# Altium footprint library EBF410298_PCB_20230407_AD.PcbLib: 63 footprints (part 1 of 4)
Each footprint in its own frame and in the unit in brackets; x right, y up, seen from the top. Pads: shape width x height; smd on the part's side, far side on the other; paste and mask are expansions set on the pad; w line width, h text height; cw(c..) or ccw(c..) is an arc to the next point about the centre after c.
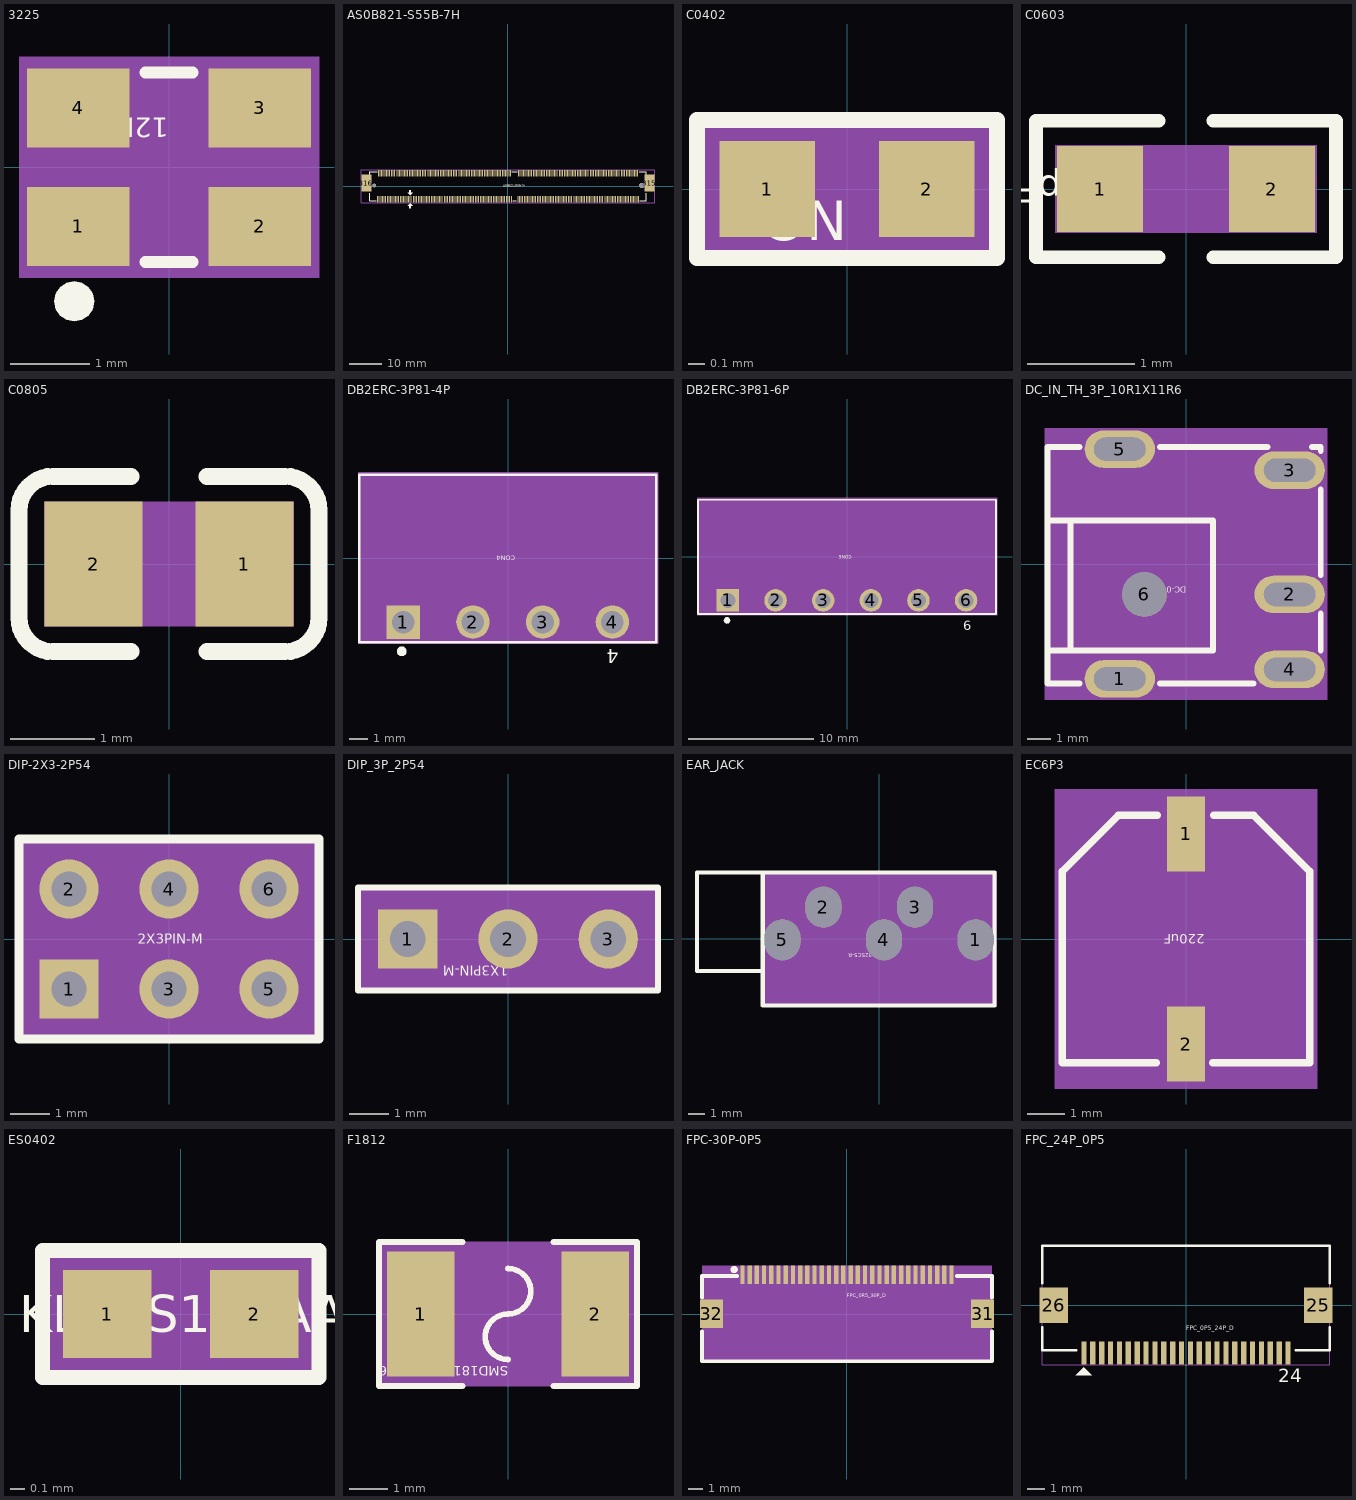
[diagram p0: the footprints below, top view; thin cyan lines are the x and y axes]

## 3225 [mm] "3225"
pads (4):
  rect 1.3x1 smd: 1(-1.15,-0.75) 2(1.15,-0.75) 3(1.15,0.75) 4(-1.15,0.75)
Top Overlay:
  dashed: -1.2,-1.955 -1.298,-1.935 -1.38,-1.88 -1.435,-1.798 -1.455,-1.7 -1.435,-1.602 -1.417,-1.575 -1.38,-1.52 -1.298,-1.465 -1.2,-1.445 -1.102,-1.465 -1.02,-1.52 -0.983,-1.575 -0.965,-1.602 -0.945,-1.7 -0.965,-1.798 -1.02,-1.88 -1.102,-1.935
  lines w0.15: -0.3,-1.2 0.3,-1.2 ; -0.3,1.2 0.3,1.2
  text "12MHz" at 0,0.625 h0.25
Top 3D Body:
  region: -1.9,1.4 -1.9,-1.4 1.9,-1.4 1.9,1.4
Mechanical 17:
  text "1" at -1.15,-0.394 h0.89
  text "3" at 1.15,1.106 h0.89
  text "2" at 1.15,-0.394 h0.89
  text "4" at -1.15,1.106 h0.89
Top Assembly:
  lines w0.15: -1.6,-1.25 -1.6,1.25 1.6,1.25 1.6,-1.25 -1.6,-1.25
3D body: height 3.81, standoff 0, extent -1.9,-1.4 1.9,1.4

## AS0B821-S55B-7H [mm] "AS0B821-S55B-7H"
pads (318):
  rect 0.3x2 smd: 1(-40,-3.95) 2(-39.75,3.95) 3(-39.5,-3.95) 4(-39.25,3.95) 5(-39,-3.95) 6(-38.75,3.95) 7(-38.5,-3.95) 8(-38.25,3.95) 9(-38,-3.95) 10(-37.75,3.95) 11(-37.5,-3.95) 12(-37.25,3.95) 13(-37,-3.95) 14(-36.75,3.95) 15(-36.5,-3.95) 16(-36.25,3.95) 17(-36,-3.95) 18(-35.75,3.95) 19(-35.5,-3.95) 20(-35.25,3.95) 21(-35,-3.95) 22(-34.75,3.95) 23(-34.5,-3.95) 24(-34.25,3.95) 25(-34,-3.95) 26(-33.75,3.95) 27(-33.5,-3.95) 28(-33.25,3.95) 29(-33,-3.95) 30(-32.75,3.95) 31(-32.5,-3.95) 32(-32.25,3.95) 33(-32,-3.95) 34(-31.75,3.95) 35(-31.5,-3.95) 36(-31.25,3.95) 37(-31,-3.95) 38(-30.75,3.95) 39(-30.5,-3.95) 40(-30.25,3.95) 41(-30,-3.95) 42(-29.75,3.95) 43(-29.5,-3.95) 44(-29.25,3.95) 45(-29,-3.95) 46(-28.75,3.95) 47(-28.5,-3.95) 48(-28.25,3.95) 49(-28,-3.95) 50(-27.75,3.95) 51(-27.5,-3.95) 52(-27.25,3.95) 53(-27,-3.95) 54(-26.75,3.95) 55(-26.5,-3.95) 56(-26.25,3.95) 57(-26,-3.95) 58(-25.75,3.95) 59(-25.5,-3.95) 60(-25.25,3.95) 61(-25,-3.95) 62(-24.75,3.95) 63(-24.5,-3.95) 64(-24.25,3.95) 65(-24,-3.95) 66(-23.75,3.95) 67(-23.5,-3.95) 68(-23.25,3.95) 69(-23,-3.95) 70(-22.75,3.95) 71(-22.5,-3.95) 72(-22.25,3.95) 73(-22,-3.95) 74(-21.75,3.95) 75(-21.5,-3.95) 76(-21.25,3.95) 77(-21,-3.95) 78(-20.75,3.95) 79(-20.5,-3.95) 80(-20.25,3.95) 81(-20,-3.95) 82(-19.75,3.95) 83(-19.5,-3.95) 84(-19.25,3.95) 85(-19,-3.95) 86(-18.75,3.95) 87(-18.5,-3.95) 88(-18.25,3.95) 89(-18,-3.95) 90(-17.75,3.95) 91(-17.5,-3.95) 92(-17.25,3.95) 93(-17,-3.95) 94(-16.75,3.95) 95(-16.5,-3.95) 96(-16.25,3.95) 97(-16,-3.95) 98(-15.75,3.95) 99(-15.5,-3.95) 100(-15.25,3.95) 101(-15,-3.95) 102(-14.75,3.95) 103(-14.5,-3.95) 104(-14.25,3.95) 105(-14,-3.95) 106(-13.75,3.95) 107(-13.5,-3.95) 108(-13.25,3.95) 109(-13,-3.95) 110(-12.75,3.95) 111(-12.5,-3.95) 112(-12.25,3.95) 113(-12,-3.95) 114(-11.75,3.95) 115(-11.5,-3.95) 116(-11.25,3.95) 117(-11,-3.95) 118(-10.75,3.95) 119(-10.5,-3.95) 120(-10.25,3.95) 121(-10,-3.95) 122(-9.75,3.95) 123(-9.5,-3.95) 124(-9.25,3.95) 125(-9,-3.95) 126(-8.75,3.95) 127(-8.5,-3.95) 128(-8.25,3.95) 129(-8,-3.95) 130(-7.75,3.95) 131(-7.5,-3.95) 132(-7.25,3.95) 133(-7,-3.95) 134(-6.75,3.95) 135(-6.5,-3.95) 136(-6.25,3.95) 137(-6,-3.95) 138(-5.75,3.95) 139(-5.5,-3.95) 140(-5.25,3.95) 141(-5,-3.95) 142(-4.75,3.95) 143(-4.5,-3.95) 144(-4.25,3.95) 145(-4,-3.95) 146(-3.75,3.95) 147(-3.5,-3.95) 148(-3.25,3.95) 149(-3,-3.95) 150(-2.75,3.95) 151(-2.5,-3.95) 152(-2.25,3.95) 153(-2,-3.95) 154(-1.75,3.95) 155(-1.5,-3.95) 156(-1.25,3.95) 157(-1,-3.95) 158(-0.75,3.95) 159(-0.5,-3.95) 160(-0.25,3.95) 161(0,-3.95) 162(0.25,3.95) 163(0.5,-3.95) 164(0.75,3.95) 165(1,-3.95) 166(3.25,3.95) 167(3,-3.95) 168(3.75,3.95) 169(3.5,-3.95) 170(4.25,3.95) 171(4,-3.95) 172(4.75,3.95) 173(4.5,-3.95) 174(5.25,3.95) 175(5,-3.95) 176(5.75,3.95) 177(5.5,-3.95) 178(6.25,3.95) 179(6,-3.95) 180(6.75,3.95) 181(6.5,-3.95) 182(7.25,3.95) 183(7,-3.95) 184(7.75,3.95) 185(7.5,-3.95) 186(8.25,3.95) 187(8,-3.95) 188(8.75,3.95) 189(8.5,-3.95) 190(9.25,3.95) 191(9,-3.95) 192(9.75,3.95) 193(9.5,-3.95) 194(10.25,3.95) 195(10,-3.95) 196(10.75,3.95) 197(10.5,-3.95) 198(11.25,3.95) 199(11,-3.95) 200(11.75,3.95) 201(11.5,-3.95) 202(12.25,3.95) 203(12,-3.95) 204(12.75,3.95) 205(12.5,-3.95) 206(13.25,3.95) 207(13,-3.95) 208(13.75,3.95) 209(13.5,-3.95) 210(14.25,3.95) 211(14,-3.95) 212(14.75,3.95) 213(14.5,-3.95) 214(15.25,3.95) 215(15,-3.95) 216(15.75,3.95) 217(15.5,-3.95) 218(16.25,3.95) 219(16,-3.95) 220(16.75,3.95) 221(16.5,-3.95) 222(17.25,3.95) 223(17,-3.95) 224(17.75,3.95) 225(17.5,-3.95) 226(18.25,3.95) 227(18,-3.95) 228(18.75,3.95) 229(18.5,-3.95) 230(19.25,3.95) 231(19,-3.95) 232(19.75,3.95) 233(19.5,-3.95) 234(20.25,3.95) 235(20,-3.95) 236(20.75,3.95) 237(20.5,-3.95) 238(21.25,3.95) 239(21,-3.95) 240(21.75,3.95) 241(21.5,-3.95) 242(22.25,3.95) 243(22,-3.95) 244(22.75,3.95) 245(22.5,-3.95) 246(23.25,3.95) 247(23,-3.95) 248(23.75,3.95) 249(23.5,-3.95) 250(24.25,3.95) 251(24,-3.95) 252(24.75,3.95) 253(24.5,-3.95) 254(25.25,3.95) 255(25,-3.95) 256(25.75,3.95) 257(25.5,-3.95) 258(26.25,3.95) 259(26,-3.95) 260(26.75,3.95) 261(26.5,-3.95) 262(27.25,3.95) 263(27,-3.95) 264(27.75,3.95) 265(27.5,-3.95) 266(28.25,3.95) 267(28,-3.95) 268(28.75,3.95) 269(28.5,-3.95) 270(29.25,3.95) 271(29,-3.95) 272(29.75,3.95) 273(29.5,-3.95) 274(30.25,3.95) 275(30,-3.95) 276(30.75,3.95) 277(30.5,-3.95) 278(31.25,3.95) 279(31,-3.95) 280(31.75,3.95) 281(31.5,-3.95) 282(32.25,3.95) 283(32,-3.95) 284(32.75,3.95) 285(32.5,-3.95) 286(33.25,3.95) 287(33,-3.95) 288(33.75,3.95) 289(33.5,-3.95) 290(34.25,3.95) 291(34,-3.95) 292(34.75,3.95) 293(34.5,-3.95) 294(35.25,3.95) 295(35,-3.95) 296(35.75,3.95) 297(35.5,-3.95) 298(36.25,3.95) 299(36,-3.95) 300(36.75,3.95) 301(36.5,-3.95) 302(37.25,3.95) 303(37,-3.95) 304(37.75,3.95) 305(37.5,-3.95) 306(38.25,3.95) 307(38,-3.95) 308(38.75,3.95) 309(38.5,-3.95) 310(39.25,3.95) 311(39,-3.95) 312(39.75,3.95) 313(39.5,-3.95) 314(40,-3.95)
  rect 3x5.15 smd: 315(43.4,1) 316(-43.4,1)
  round 1.1 hole 1.1 unplated: ""(-41,0.25)
  round 1.6 hole 1.6: ""(41,0.25)
Top Overlay:
  dashed: -29.761,-5.943 -29.761,-6.693 -30.261,-6.693 -30.261,-5.943 -30.761,-5.943 -30.011,-5.193 -29.261,-5.943
  dashed: -30.25,-2 -30.25,-1.25 -29.75,-1.25 -29.75,-2 -29.25,-2 -30,-2.75 -30.75,-2
  lines w0.254: -42.3,-2.056 -42.3,-4.45 -40.391,-4.45 ; -42.3,3.556 -42.3,4.45 -40.141,4.45 ; 1.156,4.45 2.844,4.45 ; 1.406,-4.45 2.594,-4.45 ; 40.156,4.45 42.3,4.45 42.3,3.556 ; 40.406,-4.45 42.3,-4.45 42.3,-2.056
  text "AS0B821-S55B-7H" at -1.499,-0.125 h0.25
Top 3D Body:
  lines w0.025: -45.002,-5.052 -45.002,5.052 45.002,5.052 45.002,-5.052 -45.002,-5.052
Mechanical 17:
  text "64" at -24.758,3.95 h0.64
  text "66" at -24.258,3.95 h0.64
  text "68" at -23.758,3.95 h0.64
  text "70" at -23.258,3.95 h0.64
  text "82" at -20.258,3.95 h0.64
  text "84" at -19.758,3.95 h0.64
  text "86" at -19.258,3.95 h0.64
  text "88" at -18.758,3.95 h0.64
  text "260" at 25.988,3.95 h0.64
  text "119" at -11.262,-3.95 h0.64
  text "178" at 5.488,3.95 h0.64
  text "251" at 23.238,-3.95 h0.64
  text "183" at 6.238,-3.95 h0.64
  text "180" at 5.988,3.95 h0.64
  text "293" at 33.738,-3.95 h0.64
  text "297" at 34.738,-3.95 h0.64
  text "291" at 33.238,-3.95 h0.64
  text "112" at -13.012,3.95 h0.64
  text "289" at 32.738,-3.95 h0.64
  text "295" at 34.238,-3.95 h0.64
  text "108" at -14.012,3.95 h0.64
  text "110" at -13.512,3.95 h0.64
  text "182" at 6.488,3.95 h0.64
  text "114" at -12.512,3.95 h0.64
  text "104" at -15.012,3.95 h0.64
  text "276" at 29.988,3.95 h0.64
  text "278" at 30.488,3.95 h0.64
  text "284" at 31.988,3.95 h0.64
  text "282" at 31.488,3.95 h0.64
  text "280" at 30.988,3.95 h0.64
  text "102" at -15.512,3.95 h0.64
  text "309" at 37.738,-3.95 h0.64
  text "35" at -32.008,-3.95 h0.64
  text "160" at -1.012,3.95 h0.64
  text "162" at -0.512,3.95 h0.64
  text "184" at 6.988,3.95 h0.64
  text "186" at 7.488,3.95 h0.64
  text "44" at -29.758,3.95 h0.64
  text "188" at 7.988,3.95 h0.64
  text "69" at -23.508,-3.95 h0.64
  text "190" at 8.488,3.95 h0.64
  text "245" at 21.738,-3.95 h0.64
  text "192" at 8.988,3.95 h0.64
  text "40" at -30.758,3.95 h0.64
  text "196" at 9.988,3.95 h0.64
  text "198" at 10.488,3.95 h0.64
  text "200" at 10.988,3.95 h0.64
  text "202" at 11.488,3.95 h0.64
  text "233" at 18.738,-3.95 h0.64
  text "42" at -30.258,3.95 h0.64
  text "277" at 29.738,-3.95 h0.64
  text "279" at 30.238,-3.95 h0.64
  text "281" at 30.738,-3.95 h0.64
  text "120" at -11.012,3.95 h0.64
  text "43" at -30.008,-3.95 h0.64
  text "283" at 31.238,-3.95 h0.64
  text "156" at -2.012,3.95 h0.64
  text "158" at -1.512,3.95 h0.64
  text "41" at -30.508,-3.95 h0.64
  text "49" at -28.508,-3.95 h0.64
  text "255" at 24.238,-3.95 h0.64
  text "257" at 24.738,-3.95 h0.64
  text "126" at -9.512,3.95 h0.64
  text "47" at -29.008,-3.95 h0.64
  text "261" at 25.738,-3.95 h0.64
  text "307" at 37.238,-3.95 h0.64
  text "51" at -28.008,-3.95 h0.64
  text "259" at 25.238,-3.95 h0.64
  text "215" at 14.238,-3.95 h0.64
  text "45" at -29.508,-3.95 h0.64
  text "213" at 13.738,-3.95 h0.64
  text "203" at 11.238,-3.95 h0.64
  text "179" at 5.238,-3.95 h0.64
  text "201" at 10.738,-3.95 h0.64
  text "209" at 12.738,-3.95 h0.64
  text "305" at 36.738,-3.95 h0.64
  text "207" at 12.238,-3.95 h0.64
  text "177" at 4.738,-3.95 h0.64
  text "199" at 10.238,-3.95 h0.64
  text "197" at 9.738,-3.95 h0.64
  text "219" at 15.238,-3.95 h0.64
  text "217" at 14.738,-3.95 h0.64
  text "123" at -10.262,-3.95 h0.64
  text "137" at -6.762,-3.95 h0.64
  text "139" at -6.262,-3.95 h0.64
  text "189" at 7.738,-3.95 h0.64
  text "111" at -13.262,-3.95 h0.64
  text "136" at -7.012,3.95 h0.64
  text "109" at -13.762,-3.95 h0.64
  text "134" at -7.512,3.95 h0.64
  text "191" at 8.238,-3.95 h0.64
  text "28" at -33.758,3.95 h0.64
  text "132" at -8.012,3.95 h0.64
  text "75" at -22.008,-3.95 h0.64
  text "193" at 8.738,-3.95 h0.64
  text "30" at -33.258,3.95 h0.64
  text "130" at -8.512,3.95 h0.64
  text "79" at -21.008,-3.95 h0.64
  text "71" at -23.008,-3.95 h0.64
  text "73" at -22.508,-3.95 h0.64
  text "121" at -10.762,-3.95 h0.64
  text "37" at -31.508,-3.95 h0.64
  text "5" at -39.254,-3.95 h0.64
  text "3" at -39.754,-3.95 h0.64
  text "1" at -40.254,-3.95 h0.64
  text "2" at -40.004,3.95 h0.64
  text "4" at -39.504,3.95 h0.64
  text "6" at -39.004,3.95 h0.64
  text "181" at 5.738,-3.95 h0.64
  text "252" at 23.988,3.95 h0.64
  text "250" at 23.488,3.95 h0.64
  text "256" at 24.988,3.95 h0.64
  text "254" at 24.488,3.95 h0.64
  text "246" at 22.488,3.95 h0.64
  text "244" at 21.988,3.95 h0.64
  text "223" at 16.238,-3.95 h0.64
  text "269" at 27.738,-3.95 h0.64
  text "93" at -17.508,-3.95 h0.64
  text "59" at -26.008,-3.95 h0.64
  text "60" at -25.758,3.95 h0.64
  text "103" at -15.262,-3.95 h0.64
  text "57" at -26.508,-3.95 h0.64
  text "61" at -25.508,-3.95 h0.64
  text "15" at -37.008,-3.95 h0.64
  text "13" at -37.508,-3.95 h0.64
  text "95" at -17.008,-3.95 h0.64
  text "63" at -25.008,-3.95 h0.64
  text "99" at -16.008,-3.95 h0.64
  text "55" at -27.008,-3.95 h0.64
  text "19" at -36.008,-3.95 h0.64
  text "17" at -36.508,-3.95 h0.64
  text "65" at -24.508,-3.95 h0.64
  text "23" at -35.008,-3.95 h0.64
  text "21" at -35.508,-3.95 h0.64
  text "101" at -15.762,-3.95 h0.64
  text "236" at 19.988,3.95 h0.64
  text "14" at -37.258,3.95 h0.64
  text "16" at -36.758,3.95 h0.64
  text "234" at 19.488,3.95 h0.64
  text "83" at -20.008,-3.95 h0.64
  text "76" at -21.758,3.95 h0.64
  text "85" at -19.508,-3.95 h0.64
  text "78" at -21.258,3.95 h0.64
  text "242" at 21.488,3.95 h0.64
  text "98" at -16.258,3.95 h0.64
  text "240" at 20.988,3.95 h0.64
  text "80" at -20.758,3.95 h0.64
  text "105" at -14.762,-3.95 h0.64
  text "74" at -22.258,3.95 h0.64
  text "232" at 18.988,3.95 h0.64
  text "230" at 18.488,3.95 h0.64
  text "235" at 19.238,-3.95 h0.64
  text "243" at 21.238,-3.95 h0.64
  text "77" at -21.508,-3.95 h0.64
  text "58" at -26.258,3.95 h0.64
  text "237" at 19.738,-3.95 h0.64
  text "89" at -18.508,-3.95 h0.64
  text "302" at 36.488,3.95 h0.64
  text "304" at 36.988,3.95 h0.64
  text "141" at -5.762,-3.95 h0.64
  text "144" at -5.012,3.95 h0.64
  text "154" at -2.512,3.95 h0.64
  text "159" at -1.262,-3.95 h0.64
  text "164" at -0.012,3.95 h0.64
  text "53" at -27.508,-3.95 h0.64
  text "167" at 2.238,-3.95 h0.64
  text "166" at 2.488,3.95 h0.64
  text "176" at 4.988,3.95 h0.64
  text "195" at 9.238,-3.95 h0.64
  text "194" at 9.488,3.95 h0.64
  text "205" at 11.738,-3.95 h0.64
  text "204" at 11.988,3.95 h0.64
  text "211" at 13.238,-3.95 h0.64
  text "214" at 14.488,3.95 h0.64
  text "221" at 15.738,-3.95 h0.64
  text "229" at 17.738,-3.95 h0.64
  text "228" at 17.988,3.95 h0.64
  text "239" at 20.238,-3.95 h0.64
  text "238" at 20.488,3.95 h0.64
  text "249" at 22.738,-3.95 h0.64
  text "248" at 22.988,3.95 h0.64
  text "62" at -25.258,3.95 h0.64
  text "258" at 25.488,3.95 h0.64
  text "263" at 26.238,-3.95 h0.64
  text "272" at 28.988,3.95 h0.64
  text "285" at 31.738,-3.95 h0.64
  text "288" at 32.988,3.95 h0.64
  text "294" at 34.488,3.95 h0.64
  text "299" at 35.238,-3.95 h0.64
  text "300" at 35.988,3.95 h0.64
  text "67" at -24.008,-3.95 h0.64
  text "306" at 37.488,3.95 h0.64
  text "311" at 38.238,-3.95 h0.64
  text "312" at 38.988,3.95 h0.64
  text "315" at 42.638,1 h0.64
  text "316" at -44.162,1 h0.64
  text "72" at -22.758,3.95 h0.64
  text "81" at -20.508,-3.95 h0.64
  text "87" at -19.008,-3.95 h0.64
  text "90" at -18.258,3.95 h0.64
  text "91" at -18.008,-3.95 h0.64
  text "96" at -16.758,3.95 h0.64
  text "46" at -29.258,3.95 h0.64
  text "100" at -16.012,3.95 h0.64
  text "106" at -14.512,3.95 h0.64
  text "107" at -14.262,-3.95 h0.64
  text "116" at -12.012,3.95 h0.64
  text "117" at -11.762,-3.95 h0.64
  text "122" at -10.512,3.95 h0.64
  text "128" at -9.012,3.95 h0.64
  text "135" at -7.262,-3.95 h0.64
  text "138" at -6.512,3.95 h0.64
  text "11" at -38.008,-3.95 h0.64
  text "9" at -38.254,-3.95 h0.64
  text "7" at -38.754,-3.95 h0.64
  text "8" at -38.504,3.95 h0.64
  text "10" at -38.258,3.95 h0.64
  text "12" at -37.758,3.95 h0.64
  text "18" at -36.258,3.95 h0.64
  text "39" at -31.008,-3.95 h0.64
  text "27" at -34.008,-3.95 h0.64
  text "25" at -34.508,-3.95 h0.64
  text "38" at -31.258,3.95 h0.64
  text "32" at -32.758,3.95 h0.64
  text "26" at -34.258,3.95 h0.64
  text "24" at -34.758,3.95 h0.64
  text "22" at -35.258,3.95 h0.64
  text "225" at 16.738,-3.95 h0.64
  text "33" at -32.508,-3.95 h0.64
  text "187" at 7.238,-3.95 h0.64
  text "31" at -33.008,-3.95 h0.64
  text "29" at -33.508,-3.95 h0.64
  text "275" at 29.238,-3.95 h0.64
  text "298" at 35.488,3.95 h0.64
  text "56" at -26.758,3.95 h0.64
  text "273" at 28.738,-3.95 h0.64
  text "36" at -31.758,3.95 h0.64
  text "34" at -32.258,3.95 h0.64
  text "314" at 39.238,-3.95 h0.64
  text "313" at 38.738,-3.95 h0.64
  text "131" at -8.262,-3.95 h0.64
  text "115" at -12.262,-3.95 h0.64
  text "113" at -12.762,-3.95 h0.64
  text "124" at -10.012,3.95 h0.64
  text "296" at 34.988,3.95 h0.64
  text "143" at -5.262,-3.95 h0.64
  text "152" at -3.012,3.95 h0.64
  text "292" at 33.988,3.95 h0.64
  text "231" at 18.238,-3.95 h0.64
  text "147" at -4.262,-3.95 h0.64
  text "133" at -7.762,-3.95 h0.64
  text "146" at -4.512,3.95 h0.64
  text "274" at 29.488,3.95 h0.64
  text "149" at -3.762,-3.95 h0.64
  text "253" at 23.738,-3.95 h0.64
  text "118" at -11.512,3.95 h0.64
  text "287" at 32.238,-3.95 h0.64
  text "173" at 3.738,-3.95 h0.64
  text "290" at 33.488,3.95 h0.64
  text "171" at 3.238,-3.95 h0.64
  text "148" at -4.012,3.95 h0.64
  text "247" at 22.238,-3.95 h0.64
  text "150" at -3.512,3.95 h0.64
  text "97" at -16.508,-3.95 h0.64
  text "151" at -3.262,-3.95 h0.64
  text "153" at -2.762,-3.95 h0.64
  text "286" at 32.488,3.95 h0.64
  text "155" at -2.262,-3.95 h0.64
  text "227" at 17.238,-3.95 h0.64
  text "157" at -1.762,-3.95 h0.64
  text "92" at -17.758,3.95 h0.64
  text "94" at -17.258,3.95 h0.64
  text "169" at 2.738,-3.95 h0.64
  text "142" at -5.512,3.95 h0.64
  text "175" at 4.238,-3.95 h0.64
  text "140" at -6.012,3.95 h0.64
  text "172" at 3.988,3.95 h0.64
  text "168" at 2.988,3.95 h0.64
  text "174" at 4.488,3.95 h0.64
  text "185" at 6.738,-3.95 h0.64
  text "267" at 27.238,-3.95 h0.64
  text "271" at 28.238,-3.95 h0.64
  text "52" at -27.758,3.95 h0.64
  text "54" at -27.258,3.95 h0.64
  text "265" at 26.738,-3.95 h0.64
  text "48" at -28.758,3.95 h0.64
  text "161" at -0.762,-3.95 h0.64
  text "50" at -28.258,3.95 h0.64
  text "222" at 16.488,3.95 h0.64
  text "163" at -0.262,-3.95 h0.64
  text "220" at 15.988,3.95 h0.64
  text "212" at 13.988,3.95 h0.64
  text "165" at 0.238,-3.95 h0.64
  text "210" at 13.488,3.95 h0.64
  text "218" at 15.488,3.95 h0.64
  text "216" at 14.988,3.95 h0.64
  text "127" at -9.262,-3.95 h0.64
  text "303" at 36.238,-3.95 h0.64
  text "208" at 12.988,3.95 h0.64
  text "206" at 12.488,3.95 h0.64
  text "145" at -4.762,-3.95 h0.64
  text "226" at 17.488,3.95 h0.64
  text "224" at 16.988,3.95 h0.64
  text "20" at -35.758,3.95 h0.64
  text "129" at -8.762,-3.95 h0.64
  text "301" at 35.738,-3.95 h0.64
  text "125" at -9.762,-3.95 h0.64
  text "170" at 3.488,3.95 h0.64
  text "241" at 20.738,-3.95 h0.64
  text "262" at 26.488,3.95 h0.64
  text "264" at 26.988,3.95 h0.64
  text "266" at 27.488,3.95 h0.64
  text "268" at 27.988,3.95 h0.64
  text "270" at 28.488,3.95 h0.64
  text "308" at 37.988,3.95 h0.64
  text "310" at 38.488,3.95 h0.64

## C0402 [mm] "C0402"
pads (2):
  rect 0.599x0.599 smd: 1(-0.5,0) 2(0.5,0)
Top Overlay:
  lines w0.102: -0.94,-0.432 0.94,-0.432 0.94,0.432 -0.94,0.432 -0.94,-0.432
  text "NC" at 0,-0.075 h0.25
Top 3D Body:
  region: 0.94,0.432 0.94,-0.432 -0.94,-0.432 -0.94,0.432
Mechanical 17:
  text "1" at -0.5,-0.254 h0.64
  text "2" at 0.5,-0.254 h0.64
Top Assembly:
  dashed: -0.94,-0.432 -0.94,0.432 0.94,0.432 0.94,-0.432
3D body: height 3.81, standoff 0, extent -0.94,-0.432 0.94,0.432

## C0603 [mil] "C0603"
pads (2):
  rect 31.5x31.5 smd: 1(-31.5,0) 2(31.5,0)
Top Overlay:
  lines w5: -10,-25 -55,-25 -55,25 -10,25 ; 10,-25 55,-25 55,25 10,25
  text "100pF" at -19.68,4.92 h9.84
Top 3D Body:
  region: -48,16 48,16 48,-16 -48,-16
Mechanical 17:
  text "2" at 13.5,0 h45
  text "1" at -49.5,0 h45
Top Assembly:
  text "C0603" at -117,37 h35
3D body: height 150, standoff 0, extent -48,-16 48,16

## C0805 [mm] "C0805"
pads (2):
  rect 1.16x1.47 smd: 1(0.89,0) 2(-0.89,0)
Top Overlay:
  lines w0.2: -0.45,-1.035 -1.37,-1.035 cw(c-1.37,-0.635) -1.77,-0.635 -1.77,0.635 cw(c-1.37,0.635) -1.37,1.035 -0.45,1.035 ; 0.45,-1.035 1.37,-1.035 ccw(c1.37,-0.635) 1.77,-0.635 1.77,0.635 ccw(c1.37,0.635) 1.37,1.035 0.45,1.035
  text "22uF" at -0.4,0.125 h0.25
Top 3D Body:
  region: 1.47,0.735 1.47,-0.735 -1.47,-0.735 -1.47,0.735
Mechanical 17:
  text "2" at -1.205,0 h0.79
  text "1" at 0.575,0 h0.79
3D body: height 3.81, standoff 0, extent -1.47,-0.735 1.47,0.735

## DB2ERC-3P81-4P [mm] "DB2ERC-3P81-4P"
pads (4):
  rect 1.83x1.83 hole 1.23: 1(-5.725,-3.5)
  round 1.83 hole 1.23: 2(-1.915,-3.5) 3(1.895,-3.5) 4(5.705,-3.5)
Top Overlay:
  dashed: -6.065,-5.1 -6.046,-5.198 -5.99,-5.28 -5.908,-5.336 -5.81,-5.355 -5.712,-5.336 -5.685,-5.317 -5.63,-5.28 -5.574,-5.198 -5.555,-5.1 -5.574,-5.002 -5.63,-4.92 -5.685,-4.883 -5.712,-4.865 -5.81,-4.845 -5.908,-4.865 -5.99,-4.92 -6.046,-5.002
  lines w0.15: -8.13,-4.6 8.11,-4.6 8.11,4.55 -8.13,4.55 -8.13,-4.6
  text "CON4" at 0.4,0.125 h0.25
  text "4" at 6.048,-4.975 h0.76
Top 3D Body:
  region: -8.2,4.7 -8.2,-4.7 8.2,-4.7 8.2,4.7
Mechanical 17:
  text "4" at 5.959,-3.5 h0.64
  text "3" at 2.149,-3.5 h0.64
  text "2" at -1.661,-3.5 h0.64
  text "1" at -5.471,-3.5 h0.64
3D body: height 3.81, standoff 0, extent -8.2,-4.7 8.2,4.7

## DB2ERC-3P81-6P [mm] "DB2ERC-3P81-6P"
pads (6):
  rect 1.8x1.8 hole 1.2: 1(-9.525,-3.5)
  round 1.8 hole 1.2: 2(-5.715,-3.5) 3(-1.905,-3.5) 4(1.905,-3.5) 5(5.715,-3.5) 6(9.525,-3.5)
Top Overlay:
  dashed: -9.855,-5.1 -9.836,-5.198 -9.78,-5.28 -9.698,-5.336 -9.6,-5.355 -9.502,-5.336 -9.475,-5.317 -9.42,-5.28 -9.364,-5.198 -9.345,-5.1 -9.364,-5.002 -9.42,-4.92 -9.475,-4.883 -9.502,-4.865 -9.6,-4.845 -9.698,-4.865 -9.78,-4.92 -9.836,-5.002
  lines w0.15: -11.93,-4.6 11.93,-4.6 11.93,4.55 -11.93,4.55 -11.93,-4.6
  text "CON6" at 0.4,0.125 h0.25
  text "6" at 9.283,-5.881 h0.76
Top 3D Body:
  region: -12,4.7 -12,-4.7 12,-4.7 12,4.7
Mechanical 17:
  text "5" at 5.969,-3.5 h0.64
  text "2" at -5.461,-3.5 h0.64
  text "6" at 9.779,-3.5 h0.64
  text "4" at 2.159,-3.5 h0.64
  text "3" at -1.651,-3.5 h0.64
  text "1" at -9.271,-3.5 h0.64
3D body: height 3.81, standoff 0, extent -12,-4.7 12,4.7

## DC_IN_TH_3P_10R1X11R6 [mm] "DC_IN_TH_3P_10R1X11R6"
pads (6):
  oval 3x1.6 hole 2.2 slot 1 at 90 deg: 1(-2.825,-4.9) 2(4.425,-1.3) 3(4.425,4) 4(4.425,-4.5) 5(-2.825,4.9)
  round 1.9 hole 1.9 unplated: 6(-1.775,-1.3)
Top Overlay:
  lines w0.254: -5.9,-3.7 1.15,-3.7 1.15,1.85 -5.65,1.85 -5.9,1.85 ; -4.926,-3.7 -4.926,1.85 ; -4.545,-5.1 -5.9,-5.1 -5.9,5 -4.545,5 ; -1.105,-5.1 2.887,-5.1 ; -1.105,5 3.478,5 ; 5.372,5 5.75,5 5.75,4.82 ; 5.75,-3.681 5.75,-2.119 ; 5.75,-0.481 5.75,3.182
  text "DC-044A-20A" at 0,-0.975 h0.25
Top 3D Body:
  region: -6.027,-5.802 6.027,-5.802 6.027,5.802 -6.027,5.802
Mechanical 17:
  text "3" at 4.425,3.746 h0.64
  text "2" at 4.425,-1.554 h0.64
  text "4" at 4.425,-4.754 h0.64
  text "5" at -2.825,4.646 h0.64
  text "1" at -2.825,-5.154 h0.64
  text "6" at -1.775,-1.554 h0.64
Top Assembly:
  text ".Designator" at 0.8,0 h0.91
Mechanical 25:
  dashed: -5.9,-3.6 1.05,-3.6 1.05,1.75 -5.9,1.75 -5.9,2 1.3,2 1.3,-3.85 -5.9,-3.85
3D body: height 3.81, standoff 0, extent -6.027,-5.802 6.027,5.802

## DIP-2X3-2P54 [mm] "DIP-2X3-2P54"
pads (6):
  rect 1.5x1.5 hole 0.9: 1(-2.54,-1.27)
  round 1.5 hole 0.9: 2(-2.54,1.27) 3(0,-1.27) 4(0,1.27) 5(2.54,-1.27) 6(2.54,1.27)
Top Overlay:
  lines w0.22: -3.54,2.54 -3.81,2.54 ; -3.81,2.54 3.81,2.54 3.81,-2.54 -3.81,-2.54 -3.81,2.54
  text "2X3PIN-M" at -0.8,-0.125 h0.25
Top 3D Body:
  region: -3.81,-2.54 3.81,-2.54 3.81,2.54 -3.81,2.54
Mechanical 17:
  text "5" at 2.286,-1.27 h0.64
  text "6" at 2.286,1.27 h0.64
  text "1" at -2.794,-1.27 h0.64
  text "2" at -2.794,1.27 h0.64
  text "4" at -0.254,1.27 h0.64
  text "3" at -0.254,-1.27 h0.64
Top Assembly:
  text ".Designator" at -3.683,2.464 h0.3
3D body: height 3.81, standoff 0, extent -3.81,-2.54 3.81,2.54

## DIP_3P_2P54 [mm] "DIP_3P_2P54"
pads (3):
  rect 1.5x1.5 hole 0.9: 1(-2.54,0)
  round 1.5 hole 0.9: 2(0,0) 3(2.54,0)
Top Overlay:
  lines w0.15: -3.8,-1.3 -3.8,1.3 3.8,1.3 3.8,-1.3 -3.8,-1.3
  text "1X3PIN-M" at 0,-0.675 h0.25
Top 3D Body:
  region: -3.8,-1.3 3.8,-1.3 3.8,1.3 -3.8,1.3
Mechanical 17:
  text "3" at 2.54,-0.254 h0.64
  text "2" at 0,-0.254 h0.64
  text "1" at -2.54,-0.254 h0.64
Top Assembly:
  lines w0.025: -3.8,-1.3 3.8,-1.3 3.8,1.3 -3.8,1.3 -3.8,-1.3
3D body: height 3.81, standoff 0, extent -3.8,-1.3 3.8,1.3

## EAR_JACK [mil] "EAR_JACK"
pads (5):
  oval 86x98 hole 86 slot 98 at 90 deg: 1(232.28,-1.97) 2(-133.86,76.77) 3(86.61,76.77) 4(11.81,-1.97) 5(-232.29,-1.97)
Top Overlay:
  lines w10: -282.68,-77 -437.68,-77 -437.68,160 -282.68,160 ; -279.68,-160 -279.68,160 277.32,160 277.32,-160 -279.68,-160
  text "PJ-325C5-R" at 0,-34.44 h9.84
Top 3D Body:
  region: -283.46,-163.39 283.46,-163.39 283.46,163.38 -283.46,163.38
Mechanical 17:
  text "3" at 86.61,66.77 h25
  text "4" at 11.81,-11.97 h25
  text "1" at 232.28,-11.97 h25
  text "2" at -133.86,66.77 h25
  text "5" at -232.29,-11.97 h25
Top Assembly:
  dashed: -283.46,163.38 -283.46,-163.39 283.46,-163.39 283.46,163.38
  text ".Designator" at -440.72,172.03 h11.81
3D body: height 150, standoff 0, extent -283.46,-163.39 283.46,163.38

## EC6P3 [mm] "EC6P3"
pads (2):
  rect 1.001x1.999 smd: 1(0,2.8) 2(0,-2.8)
Top Overlay:
  lines w0.2: -0.787,-3.3 -3.3,-3.3 -3.3,1.8 -1.8,3.3 -0.762,3.3 ; 0.711,-3.3 3.3,-3.3 3.3,1.8 1.8,3.3 0.737,3.3
  text "220uF" at 0.5,0.125 h0.25
Top 3D Body:
  region: -3.5,4 -3.5,-4 3.5,-4 3.5,4
Mechanical 17:
  text "2" at 0.356,-2.8 h0.89
  text "1" at 0.356,2.8 h0.89
3D body: height 3.81, standoff 0, extent -3.5,-4 3.5,4

## ES0402 [mm] "ES0402"
pads (2):
  rect 0.599x0.599 smd: 1(-0.5,0) 2(0.5,0)
Top Overlay:
  lines w0.102: -0.94,-0.432 0.94,-0.432 0.94,0.432 -0.94,0.432 -0.94,-0.432
  text "KLXES15AAA1" at -1.1,-0.125 h0.25
Top 3D Body:
  region: 0.94,0.432 0.94,-0.432 -0.94,-0.432 -0.94,0.432
Mechanical 17:
  text "2" at 0.246,0 h0.64
  text "1" at -0.754,0 h0.64
Top Assembly:
  dashed: -0.94,-0.432 -0.94,0.432 0.94,0.432 0.94,-0.432
3D body: height 3.81, standoff 0, extent -0.94,-0.432 0.94,0.432

## F1812 [mm] "F1812"
pads (2):
  rect 1.78x3.3 smd: 1(-2.305,0) 2(2.305,0)
Top Overlay:
  lines w0.15: -1.2,-1.9 -3.4,-1.9 -3.4,1.9 -1.2,1.9 ; 0,-1.2 cw(c0,-0.6) 0,0 ccw(c0,0.6) 0,1.2 ; 1.2,-1.9 3.4,-1.9 3.4,1.9 1.2,1.9
  text "SMD1812P200TF16" at 0,-1.375 h0.25
Top 3D Body:
  region: -3.4,-1.9 3.4,-1.9 3.4,1.9 -3.4,1.9
Mechanical 17:
  text "2" at 2.305,-0.122 h0.3
  text "1" at -2.305,-0.122 h0.3
3D body: height 3.81, standoff 0, extent -3.4,-1.9 3.4,1.9

## FPC-30P-0P5 [mm] "FPC-30P-0P5"
pads (32):
  rect 0.3x1.3 smd: 1(-7.25,2.733) 2(-6.75,2.733) 3(-6.25,2.733) 4(-5.75,2.733) 5(-5.25,2.733) 6(-4.75,2.733) 7(-4.25,2.733) 8(-3.75,2.733) 9(-3.25,2.733) 10(-2.75,2.733) 11(-2.25,2.733) 12(-1.75,2.733) 13(-1.25,2.733) 14(-0.75,2.733) 15(-0.25,2.733) 16(0.25,2.733) 17(0.75,2.733) 18(1.25,2.733) 19(1.75,2.733) 20(2.25,2.733) 21(2.75,2.733) 22(3.25,2.733) 23(3.75,2.733) 24(4.25,2.733) 25(4.75,2.733) 26(5.25,2.733) 27(5.75,2.733) 28(6.25,2.733) 29(6.75,2.733) 30(7.25,2.733)
  rect 1.6x2 smd: 31(9.4,0.032) 32(-9.4,0.032)
Top Overlay:
  circle w0.254: c-7.827,3.096 r0.127
  lines w0.254: -10.05,-1.199 -10.05,-3.257 ; -10.05,1.164 -10.05,2.652 -7.631,2.652 ; 7.631,2.652 10.05,2.652 10.05,1.164 ; 10.05,-1.199 10.05,-3.268 -10.04,-3.268 -10.05,-3.257 ; -10.05,-3.257 -10.05,-3.257
  text "FPC_0R5_30P_D" at 0,1.175 h0.25
Top 3D Body:
  region: 10.052,-3.35 10.052,3.35 -10.052,3.35 -10.052,-3.35
Mechanical 17:
  text "14" at -0.75,3.749 h0.64
  text "1" at -7.25,3.241 h0.64
  text "2" at -6.75,3.241 h0.64
  text "3" at -6.25,3.241 h0.64
  text "4" at -5.75,3.241 h0.64
  text "5" at -5.25,3.241 h0.64
  text "31" at 8.89,0.112 h0.64
  text "32" at -10.16,0.112 h0.64
  text "6" at -4.75,3.241 h0.64
  text "7" at -4.25,3.241 h0.64
  text "8" at -3.75,3.241 h0.64
  text "16" at 0.25,3.749 h0.64
  text "25" at 4.75,3.749 h0.64
  text "19" at 1.75,3.749 h0.64
  text "22" at 3.25,3.749 h0.64
  text "28" at 6.25,3.749 h0.64
  text "13" at -1.25,3.749 h0.64
  text "9" at -3.25,3.241 h0.64
  text "10" at -2.75,3.749 h0.64
  text "11" at -2.25,3.749 h0.64
  text "12" at -1.75,3.749 h0.64
  text "15" at -0.25,3.749 h0.64
  text "17" at 0.75,3.749 h0.64
  text "18" at 1.25,3.749 h0.64
  text "20" at 2.25,3.749 h0.64
  text "21" at 2.75,3.749 h0.64
  text "23" at 3.75,3.749 h0.64
  text "24" at 4.25,3.749 h0.64
  text "26" at 5.25,3.749 h0.64
  text "27" at 5.75,3.749 h0.64
  text "29" at 6.75,3.749 h0.64
  text "30" at 7.25,3.749 h0.64
3D body: height 3.81, standoff 0, extent -10.052,-3.35 10.052,3.35

## FPC_24P_0P5 [mm] "FPC_24P_0P5"
pads (26):
  rect 0.3x1.3 smd: 1(-5.75,-2.701) 2(-5.25,-2.701) 3(-4.75,-2.701) 4(-4.25,-2.701) 5(-3.75,-2.701) 6(-3.25,-2.701) 7(-2.75,-2.701) 8(-2.25,-2.701) 9(-1.75,-2.701) 10(-1.25,-2.701) 11(-0.75,-2.701) 12(-0.25,-2.701) 13(0.25,-2.701) 14(0.75,-2.701) 15(1.25,-2.701) 16(1.75,-2.701) 17(2.25,-2.701) 18(2.75,-2.701) 19(3.25,-2.701) 20(3.75,-2.701) 21(4.25,-2.701) 22(4.75,-2.701) 23(5.25,-2.701) 24(5.75,-2.701)
  rect 1.6x2 smd: 25(7.45,0.001) 26(-7.45,0.001)
Top Overlay:
  dashed: -6.199,-3.95 -5.301,-3.95 -5.75,-3.501
  lines w0.15: -8.1,-1.25 -8.1,-2.55 -6.2,-2.55 ; -8.1,1.25 -8.1,3.35 8.1,3.35 8.1,1.25 ; 6.2,-2.55 8.1,-2.55 8.1,-1.25
  text "FPC_0P5_24P_D" at 0,-1.424 h0.25
  text "24" at 5.2,-4.35 h0.76
Top 3D Body:
  lines w0.025: -8.1,-3.35 -8.1,3.35 8.1,3.35 8.1,-3.35 -8.1,-3.35
Mechanical 17:
  text "12" at -0.25,-3.209 h0.64
  text "11" at -0.75,-3.209 h0.64
  text "8" at -2.25,-2.955 h0.64
  text "7" at -2.75,-2.955 h0.64
  text "6" at -3.25,-2.955 h0.64
  text "5" at -3.75,-2.955 h0.64
  text "4" at -4.25,-2.955 h0.64
  text "26" at -7.45,-0.507 h0.64
  text "23" at 5.25,-3.209 h0.64
  text "24" at 5.75,-3.209 h0.64
  text "25" at 7.45,-0.507 h0.64
  text "10" at -1.25,-3.209 h0.64
  text "9" at -1.75,-2.955 h0.64
  text "22" at 4.75,-3.209 h0.64
  text "15" at 1.25,-3.209 h0.64
  text "1" at -5.75,-2.955 h0.64
  text "2" at -5.25,-2.955 h0.64
  text "3" at -4.75,-2.955 h0.64
  text "21" at 4.25,-3.209 h0.64
  text "20" at 3.75,-3.209 h0.64
  text "19" at 3.25,-3.209 h0.64
  text "18" at 2.75,-3.209 h0.64
  text "17" at 2.25,-3.209 h0.64
  text "16" at 1.75,-3.209 h0.64
  text "14" at 0.75,-3.209 h0.64
  text "13" at 0.25,-3.209 h0.64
